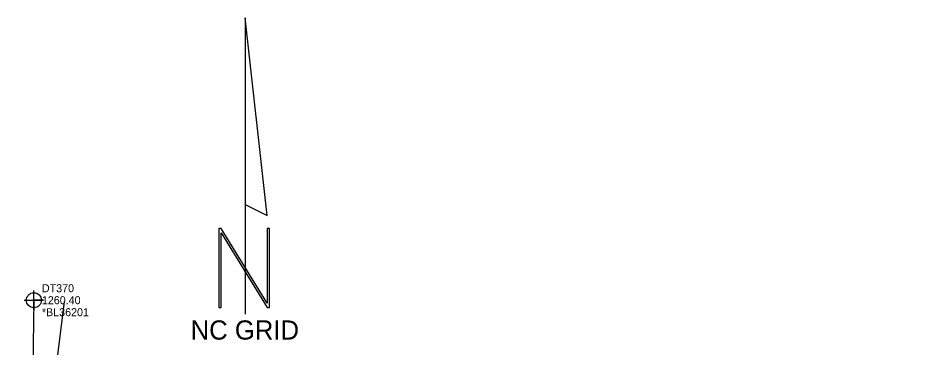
# Model space of a CAD drawing. Extents: x 1390773 to 1392296, y 959928 to 960736.
# Drawn here: x 1391644.1 to 1391924, y 960479.4 to 960582.3 of the extents above; entities that cross this region are included whole.
import ezdxf

# ---------------------------------------------------------------- set-up
doc = ezdxf.new("R2010")
doc.units = 0
for name, color, linetype in [('CTL North Arrow NAD 83 NA 2011 CELL', 7, 'Continuous'), ('Exist Hydro Jurisdictional Stream or Body of Water', 7, 'Continuous'), ('Exist Hydro Stream or Body of Water Cogo Comment', 7, 'Continuous'), ('Exist Hydro Stream or Body of Water Cogo Elevation', 7, 'Continuous'), ('Exist Hydro Stream or Body of Water Cogo Number', 7, 'Continuous'), ('Exist Hydro Stream or Body of Water Cogo Point CELL', 7, 'Continuous'), ('Exist Vegetation Woods Line', 7, 'Continuous')]:
    doc.layers.add(name, color=color, linetype=linetype)

msp = doc.modelspace()

# ---------------------------------------------------------------- linework, layer by layer
at = {"layer": 'CTL North Arrow NAD 83 NA 2011 CELL'}
msp.add_line((1391715.24, 960495.05), (1391715.24, 960495.05), dxfattribs=at)
for points in [[(1391715.09, 960582.34), (1391715.09, 960524.01), (1391721.96, 960520.57)], [(1391706.86, 960491.79), (1391707.55, 960491.79), (1391707.55, 960515.11), (1391721.96, 960491.79), (1391722.65, 960491.79), (1391722.65, 960516.47), (1391721.96, 960516.47), (1391721.96, 960493.15), (1391707.55, 960516.47), (1391706.86, 960516.47)]]:
    msp.add_lwpolyline(points, close=True, dxfattribs=at)
msp.add_lwpolyline([(1391715.09, 960524.01), (1391715.09, 960489.71)], dxfattribs=at)
at = {"layer": 'Exist Hydro Jurisdictional Stream or Body of Water'}
msp.add_lwpolyline([(1391649.06, 960494.04), (1391648.63, 960466.55), (1391627.2, 960433.7), (1391623.14, 960411.17), (1391625.85, 960360.36), (1391624.5, 960352.95)], dxfattribs=at)
at = {"layer": 'Exist Hydro Stream or Body of Water Cogo Point CELL'}
msp.add_lwpolyline([(1391646.06, 960494.04), (1391652.06, 960494.04), (1391649.06, 960494.04), (1391649.06, 960491.04), (1391649.06, 960497.04)], dxfattribs=at)
msp.add_circle((1391649.06, 960494.04), 2.34, dxfattribs=at)
at = {"layer": 'Exist Vegetation Woods Line'}
msp.add_lwpolyline([(1391924, 960170.47), (1391835.6, 960211.5), (1391761.23, 960261.63), (1391710.07, 960309.24), (1391644.93, 960365.54), (1391630.28, 960377.24), (1391631.75, 960409.9), (1391642.16, 960442.2), (1391654.83, 960463.47), (1391658.63, 960493.66)], dxfattribs=at)

# ---------------------------------------------------------------- texts
at = {"layer": 'CTL North Arrow NAD 83 NA 2011 CELL'}
msp.add_text('NC GRID', height=6, dxfattribs=at).set_placement((1391698.01, 960481.72))
at = {"layer": 'Exist Hydro Stream or Body of Water Cogo Comment'}
msp.add_text('*BL36201', height=2.5, dxfattribs=at).set_placement((1391651.56, 960489.04))
at = {"layer": 'Exist Hydro Stream or Body of Water Cogo Elevation'}
msp.add_text('1260.40', height=2.5, dxfattribs=at).set_placement((1391651.56, 960492.79))
at = {"layer": 'Exist Hydro Stream or Body of Water Cogo Number'}
msp.add_text('DT370', height=2.5, dxfattribs=at).set_placement((1391651.56, 960496.54))

doc.saveas('drawing.dxf')
